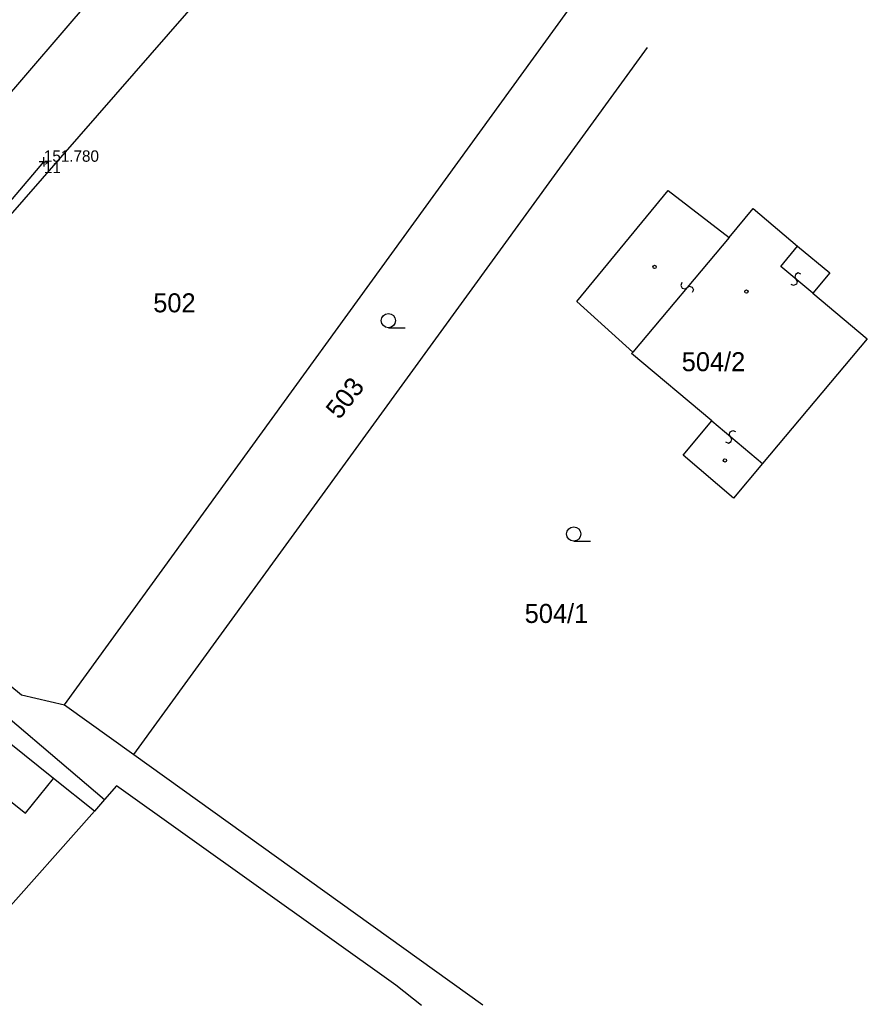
# Model space of a CAD drawing. Extents: x -748509 to -748117, y -967868 to -967533.
# Drawn here: x -748161.4 to -748116.8, y -967713.4 to -967661.4 of the extents above; entities that cross this region are included whole.
import ezdxf

# ---------------------------------------------------------------- set-up
doc = ezdxf.new("R2010")
doc.units = 0
for name, color, linetype in [('Body polohopisu', 7, 'Continuous'), ('KM', 7, 'Continuous'), ('Rozhraní ploch', 7, 'Continuous'), ('Vnitřní kresba', 7, 'Continuous'), ('Výšky bodů', 7, 'Continuous'), ('Čísla bodů', 7, 'Continuous')]:
    doc.layers.add(name, color=color, linetype=linetype)

msp = doc.modelspace()

# ---------------------------------------------------------------- linework, layer by layer
at = {"layer": 'Body polohopisu'}
for q in [(-748160.14, -967668.6), (-748160.39, -967668.85), (-748159.89, -967668.85), (-748160.14, -967669.1)]:
    msp.add_line((-748160.14, -967668.85), q, dxfattribs=at)
at = {"layer": 'KM'}
for p, q in [((-748163.76, -967667.39), (-748146.37, -967647.14)), ((-748159.06, -967697.45), (-748131.85, -967659.94)), ((-748155.4, -967700.07), (-748128.36, -967662.83)), ((-748141.997, -967677.59), (-748141.122, -967677.59)), ((-748132.236, -967688.83), (-748131.361, -967688.83)), ((-748159.06, -967697.45), (-748155.4, -967700.07)), ((-748155.4, -967700.07), (-748137.02, -967713.25)), ((-748156.94, -967702.44), (-748157.48, -967703.06)), ((-748157.48, -967703.06), (-748166.66, -967713.38)), ((-748140.25, -967713.283), (-748141.61, -967712.22))]:
    msp.add_line(p, q, dxfattribs=at)
for points in [[(-748143.1, -967650.08), (-748174.48, -967686.04), (-748161.31, -967696.92), (-748159.06, -967697.45)], [(-748124.06, -967672.84), (-748122.78, -967671.32), (-748120.45, -967673.29), (-748118.75, -967674.7), (-748119.65, -967675.77), (-748116.78, -967678.18), (-748122.3, -967684.75), (-748123.83, -967686.57), (-748126.47, -967684.3), (-748124.97, -967682.5), (-748129.19, -967678.95), (-748129.13, -967678.88), (-748132.08, -967676.21), (-748127.26, -967670.37), (-748124.06, -967672.84)], [(-748165.13, -967696.92), (-748164.43, -967696.09), (-748156.94, -967702.44)], [(-748157.48, -967703.06), (-748159.64, -967701.33), (-748165.13, -967696.92)], [(-748141.61, -967712.22), (-748156.31, -967701.72), (-748156.94, -967702.44)]]:
    msp.add_lwpolyline(points, dxfattribs=at)
for centre, radius in [((-748127.983, -967674.39), 0.0875), ((-748123.143, -967675.69), 0.0875), ((-748141.996, -967677.215), 0.375), ((-748124.273, -967684.58), 0.0875), ((-748132.236, -967688.455), 0.375)]:
    msp.add_circle(centre, radius, dxfattribs=at)
at = {"layer": 'Rozhraní ploch'}
msp.add_lwpolyline([(-748189.24, -967702.13), (-748176.77, -967687.72), (-748169.67, -967680.09), (-748160.14, -967668.85)], dxfattribs=at)
at = {"layer": 'Vnitřní kresba'}
for p, q in [((-748124.06, -967672.84), (-748129.13, -967678.88)), ((-748121.33, -967674.37), (-748120.45, -967673.29)), ((-748119.65, -967675.77), (-748121.33, -967674.37)), ((-748124.97, -967682.5), (-748122.3, -967684.75)), ((-748168.2, -967697.53), (-748161.1, -967703.16)), ((-748161.1, -967703.16), (-748159.64, -967701.33))]:
    msp.add_line(p, q, dxfattribs=at)
for points in [[(-748120.273, -967674.763), (-748120.42, -967674.705), (-748120.565, -967674.786), (-748120.598, -967674.934), (-748120.468, -967675.153), (-748120.512, -967675.299), (-748120.658, -967675.366), (-748120.791, -967675.307)], [(-748126.54, -967675.212), (-748126.598, -967675.359), (-748126.518, -967675.504), (-748126.37, -967675.538), (-748126.15, -967675.408), (-748126.005, -967675.452), (-748125.938, -967675.599), (-748125.998, -967675.732)], [(-748124.241, -967683.605), (-748124.094, -967683.663), (-748123.948, -967683.583), (-748123.915, -967683.435), (-748124.043, -967683.215), (-748123.999, -967683.069), (-748123.852, -967683.004), (-748123.719, -967683.063)]]:
    msp.add_lwpolyline(points, dxfattribs=at)

# ---------------------------------------------------------------- texts
at = {"layer": 'KM'}
for s, p in [('502', (-748154.38, -967676.78)), ('504/2', (-748126.55, -967679.88)), ('504/1', (-748134.82, -967693.14))]:
    msp.add_text(s, height=1, dxfattribs=at).set_placement(p)
msp.add_text('503', height=1, rotation=52, dxfattribs=at).set_placement((-748144.584, -967682.472))
at = {"layer": 'Výšky bodů'}
msp.add_text('151.780', height=0.6, dxfattribs=at).set_placement((-748160.14, -967668.85))
at = {"layer": 'Čísla bodů'}
msp.add_text('11', height=0.6, dxfattribs=at).set_placement((-748160.14, -967669.45))

doc.saveas('drawing.dxf')
